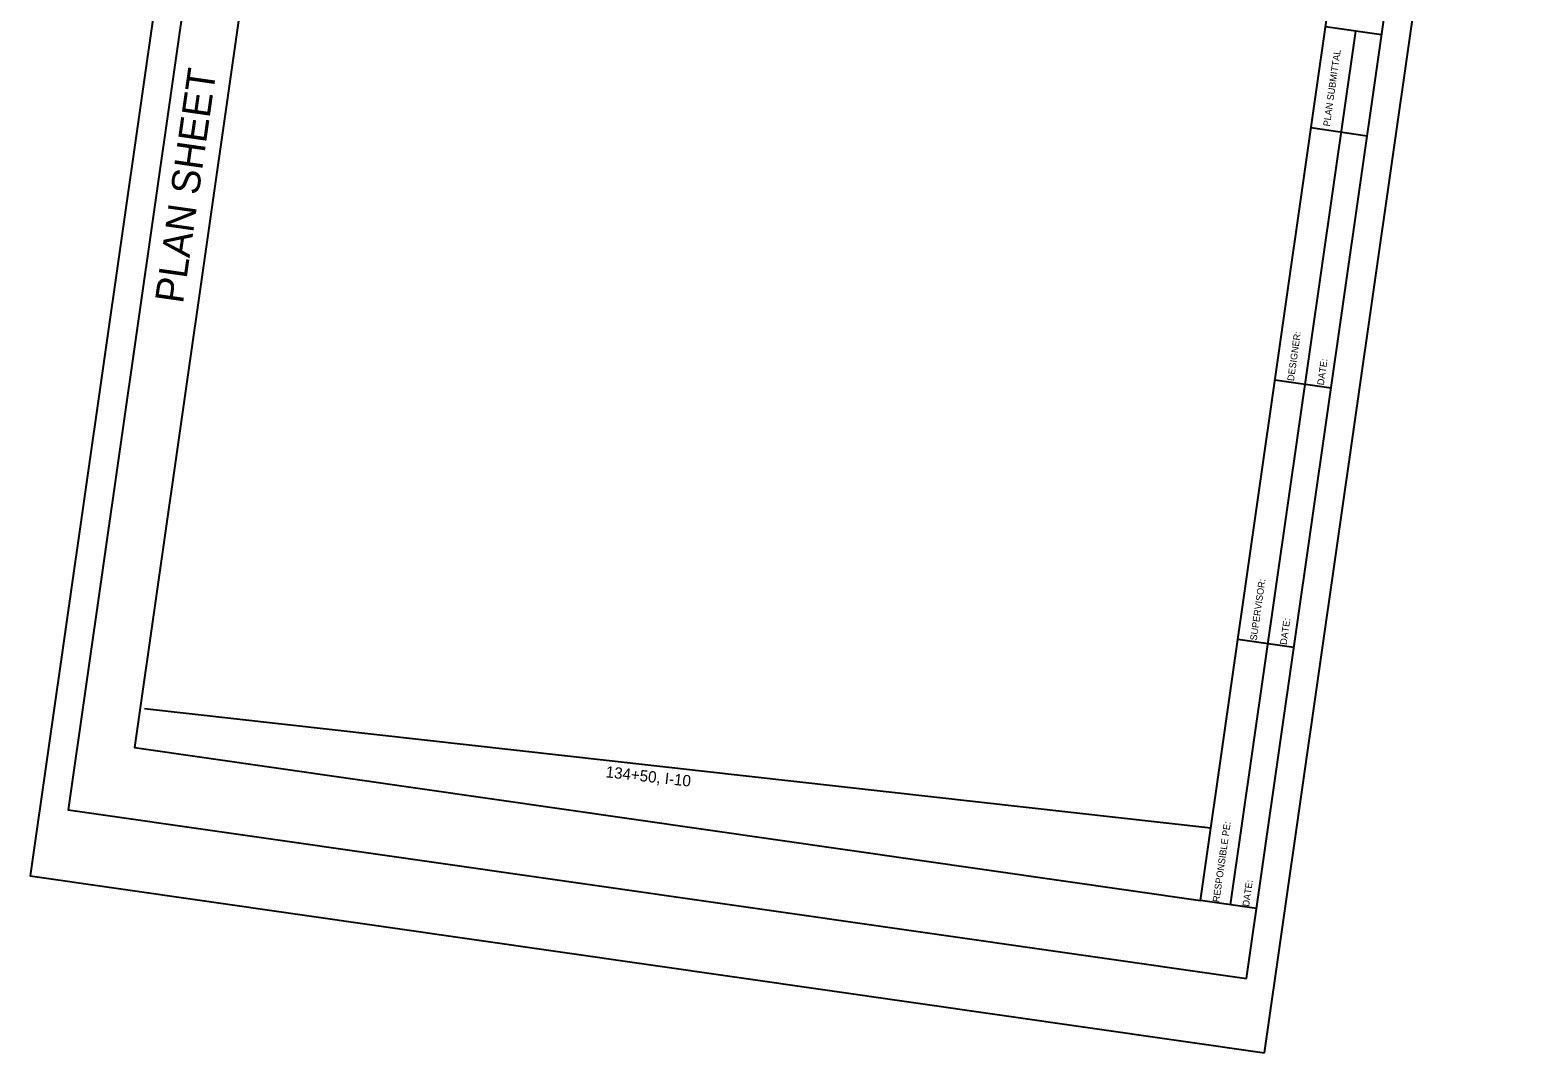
# Model space of a CAD drawing. Extents: x 1797205 to 1798536, y 248101 to 249940.
# Drawn here: x 1797205 to 1798536, y 248101 to 249003 of the extents above; entities that cross this region are included whole.
import ezdxf

# ---------------------------------------------------------------- set-up
doc = ezdxf.new("R2010")
doc.units = 0
for name, color, linetype in [('29', 7, 'Continuous'), ('ANNO-SHT', 7, 'Continuous'), ('ANNO-TXT', 7, 'Continuous'), ('AXIS', 7, 'Continuous'), ('Level 62', 7, 'Continuous'), ('SHT-BDR', 7, 'Continuous'), ('SHT-BNDRY', 7, 'Continuous')]:
    doc.layers.add(name, color=color, linetype=linetype)

msp = doc.modelspace()

# ---------------------------------------------------------------- linework, layer by layer
at = {"layer": '29'}
msp.add_line((1797306.5, 248404.6), (1798247, 248299.3), dxfattribs=at)
at = {"layer": 'Level 62'}
msp.add_lwpolyline([(1798294.4, 248101), (1798535.5, 249783.9), (1797446.7, 249939.9), (1797205.5, 248257.1)], close=True, dxfattribs=at)
at = {"layer": 'SHT-BDR'}
msp.add_lwpolyline([(1798237.8, 248235.4), (1798450.6, 249720.2), (1797510.2, 249855), (1797297.4, 248370.2)], close=True, dxfattribs=at)
at = {"layer": 'SHT-BNDRY'}
for p, q in [((1798264.5, 248231.6), (1798374.9, 249001.9)), ((1798397.7, 248998.6), (1798348.2, 249005.7)), ((1798384.9, 248909.3), (1798335.4, 248916.4)), ((1798353.1, 248687), (1798303.5, 248694.1)), ((1798270.8, 248465.7), (1798320.3, 248458.6)), ((1798287.3, 248228.3), (1798237.8, 248235.4))]:
    msp.add_line(p, q, dxfattribs=at)
msp.add_lwpolyline([(1798278.5, 248166.5), (1798507.2, 249762.7), (1797467.9, 249911.6), (1797239.1, 248315.4)], close=True, dxfattribs=at)

# ---------------------------------------------------------------- texts
at = {"layer": 'ANNO-SHT'}
for s, height, rotation, p in [('               PLAN SHEET               ', 24.998, 81.8439, (1797320.5, 248623)), ('134+50, I-10', 10, 353.6129, (1797712.8, 248344))]:
    msp.add_text(s, height=height, rotation=rotation, dxfattribs=at).set_placement(p)
at = {"layer": 'ANNO-TXT'}
for s, p in [('PLAN SUBMITTAL', (1798352, 248917.5)), ('DESIGNER:', (1798320.3, 248693)), ('DATE:', (1798346.7, 248689.3)), ('SUPERVISOR:', (1798287.5, 248464.2)), ('DATE:', (1798313.9, 248460.4)), ('RESPONSIBLE PE:', (1798254.5, 248233.5)), ('DATE:', (1798280.8, 248229.7))]:
    msp.add_text(s, height=6, rotation=81.8439, dxfattribs=at).set_placement(p)
at = {"layer": 'AXIS'}
msp.add_text('-', height=3.341328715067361e-18, rotation=134.974, dxfattribs=at).set_placement((1798188.3, 248242.5))

doc.saveas('drawing.dxf')
